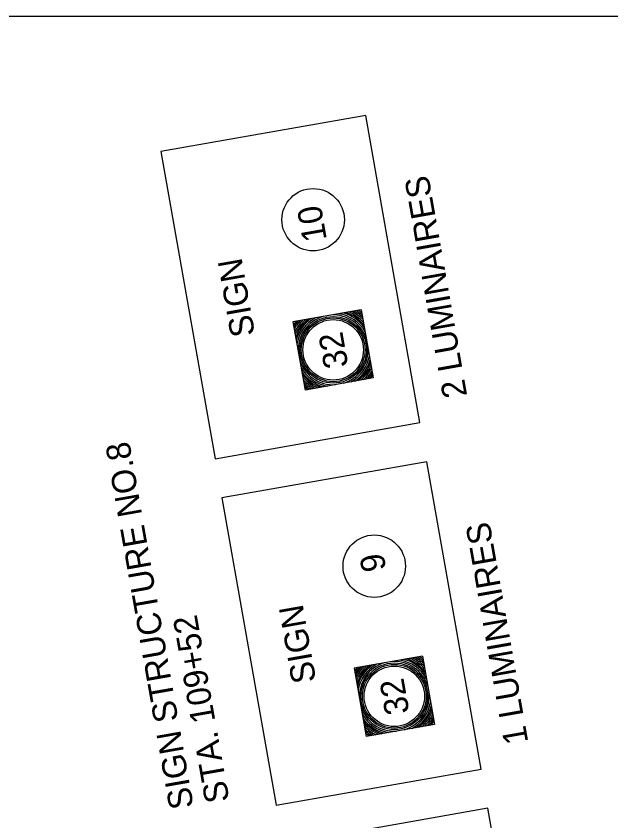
# Model space of a CAD drawing. Extents: x 36 to 2622, y -5330 to 219.
# Drawn here: x 679.8 to 753.4, y -4850.5 to -4750.8 of the extents above; entities that cross this region are included whole.
import ezdxf

# ---------------------------------------------------------------- set-up
doc = ezdxf.new("R2010")
doc.units = 0
doc.layers.add('1', color=7, linetype='Continuous')
doc.layers.add('2', color=7, linetype='Continuous')

msp = doc.modelspace()

# ---------------------------------------------------------------- linework, layer by layer
at = {"layer": '1'}
msp.add_line((75.856, -4750.83), (861.856, -4750.83), dxfattribs=at)
at = {"layer": '2'}
for points in [[(729.765, -4801.15), (723.058, -4763.122), (697.705, -4767.592), (704.411, -4805.62)], [(737.324, -4844.036), (730.618, -4806.01), (705.264, -4810.48), (711.971, -4848.506)], [(744.884, -4886.923), (738.177, -4848.895), (712.823, -4853.365), (719.53, -4891.392)]]:
    msp.add_lwpolyline(points, close=True, dxfattribs=at)
for points in [[(722.503, -4787.175), (714.053, -4788.665)], [(722.503, -4787.175), (723.992, -4795.627)], [(714.053, -4788.665), (715.542, -4797.117)], [(723.992, -4795.627), (715.542, -4797.117)], [(730.062, -4830.061), (721.615, -4831.55)], [(730.062, -4830.061), (731.552, -4838.513)], [(721.615, -4831.55), (723.104, -4840.002)], [(731.552, -4838.513), (723.104, -4840.002)]]:
    msp.add_lwpolyline(points, dxfattribs=at)
for centre, radius in [((716.546, -4776.037), 3.861), ((719.026, -4792.144), 4.125), ((719.026, -4792.144), 3.945), ((719.026, -4792.144), 3.739), ((724.105, -4818.923), 3.861), ((726.586, -4835.03), 4.125), ((726.586, -4835.03), 3.945), ((726.586, -4835.03), 3.739)]:
    msp.add_circle(centre, radius, dxfattribs=at)
for centre, radius, start, end in [((719.026, -4792.144), 4.319, 106.90383, 183.62104), ((719.026, -4792.144), 4.319, 16.90383, 93.09616), ((719.026, -4792.144), 4.529, 28.77474, 81.22525), ((719.026, -4792.144), 4.73, 34.96904, 75.03095), ((719.026, -4792.144), 4.884, 38.60357, 71.39642), ((719.026, -4792.144), 5.062, 42.10219, 67.8978), ((719.026, -4792.144), 5.257, 45.33768, 64.66231), ((719.026, -4792.144), 5.445, 48.04141, 61.95858), ((719.026, -4792.144), 5.617, 50.23096, 59.76903), ((719.026, -4792.144), 5.796, 52.28011, 57.71988), ((719.026, -4792.144), 5.796, 142.28011, 147.78717), ((719.026, -4792.144), 5.617, 140.23096, 149.84136), ((719.026, -4792.144), 5.445, 138.04141, 152.03679), ((719.026, -4792.144), 5.257, 135.33768, 154.74865), ((719.026, -4792.144), 5.062, 132.10219, 157.9954), ((719.026, -4792.144), 4.884, 128.60357, 161.50876), ((719.026, -4792.144), 4.73, 124.96904, 165.16259), ((719.026, -4792.144), 4.529, 118.77474, 171.40597), ((719.026, -4792.144), 4.319, 286.37895, 3.09616), ((719.026, -4792.144), 4.529, 298.59402, 351.22526), ((719.026, -4792.144), 4.319, 196.37895, 273.62103), ((719.026, -4792.144), 4.73, 304.8374, 345.03095), ((719.026, -4792.144), 4.884, 308.49123, 341.39643), ((719.026, -4792.144), 4.529, 208.59402, 261.40597), ((719.026, -4792.144), 4.73, 214.8374, 255.16259), ((719.026, -4792.144), 5.062, 312.00458, 337.8978), ((719.026, -4792.144), 5.257, 315.25134, 334.66231), ((719.026, -4792.144), 5.445, 317.96319, 331.95858), ((719.026, -4792.144), 5.617, 320.15863, 329.76903), ((719.026, -4792.144), 4.884, 218.49123, 251.50876), ((719.026, -4792.144), 5.062, 222.00458, 247.99539), ((719.026, -4792.144), 5.257, 225.25134, 244.74864), ((719.026, -4792.144), 5.796, 322.21282, 327.71989), ((719.026, -4792.144), 5.445, 227.96319, 242.03679), ((719.026, -4792.144), 5.617, 230.15863, 239.84136), ((719.026, -4792.144), 5.796, 232.21282, 237.78717), ((726.586, -4835.03), 4.319, 106.90383, 183.62104), ((726.586, -4835.03), 4.319, 16.90383, 93.09616), ((726.586, -4835.03), 4.529, 28.77474, 81.22525), ((726.586, -4835.03), 4.73, 34.96904, 75.03095), ((726.586, -4835.03), 4.884, 38.60357, 71.39642), ((726.586, -4835.03), 5.062, 42.10219, 67.8978), ((726.586, -4835.03), 5.257, 45.33768, 64.66231), ((726.586, -4835.03), 5.445, 48.04141, 61.95858), ((726.586, -4835.03), 5.617, 50.23096, 59.76903), ((726.586, -4835.03), 5.796, 52.28011, 57.71988), ((726.586, -4835.03), 5.796, 142.28011, 147.78717), ((726.586, -4835.03), 5.617, 140.23096, 149.84136), ((726.586, -4835.03), 5.445, 138.04141, 152.03679), ((726.586, -4835.03), 5.257, 135.33768, 154.74865), ((726.586, -4835.03), 5.062, 132.10219, 157.9954), ((726.586, -4835.03), 4.884, 128.60357, 161.50876), ((726.586, -4835.03), 4.73, 124.96904, 165.16259), ((726.586, -4835.03), 4.529, 118.77474, 171.40597), ((726.586, -4835.03), 4.319, 286.37895, 3.09616), ((726.586, -4835.03), 4.529, 298.59402, 351.22526), ((726.586, -4835.03), 4.319, 196.37895, 273.62103), ((726.586, -4835.03), 4.73, 304.8374, 345.03095), ((726.586, -4835.03), 4.884, 308.49123, 341.39643), ((726.586, -4835.03), 4.529, 208.59402, 261.40597), ((726.586, -4835.03), 4.73, 214.8374, 255.16259), ((726.586, -4835.03), 5.062, 312.00458, 337.8978), ((726.586, -4835.03), 5.257, 315.25134, 334.66231), ((726.586, -4835.03), 5.445, 317.96319, 331.95858), ((726.586, -4835.03), 5.617, 320.15863, 329.76903), ((726.586, -4835.03), 4.884, 218.49123, 251.50876), ((726.586, -4835.03), 5.062, 222.00458, 247.99539), ((726.586, -4835.03), 5.257, 225.25134, 244.74864), ((726.586, -4835.03), 5.796, 322.21282, 327.71989), ((726.586, -4835.03), 5.445, 227.96319, 242.03679), ((726.586, -4835.03), 5.617, 230.15863, 239.84136), ((726.586, -4835.03), 5.796, 232.21282, 237.78717)]:
    msp.add_arc(centre, radius, start, end, dxfattribs=at)

# ---------------------------------------------------------------- texts
for s, height, rotation, p in [('2 LUMINAIRES', 2.99549, 99.99999, (735.616, -4797.819)), ('10', 2.9955, 100, (718.255, -4778.49)), ('SIGN', 2.9955, 100, (709.372, -4790.258)), ('32', 2.9955, 100, (720.913, -4794.15)), ('SIGN STRUCTURE NO.8', 2.99549, 99.99999, (701.782, -4848.722)), ('1 LUMINAIRES', 2.99549, 99.99999, (743.176, -4840.705)), ('9', 2.995, 100, (725.598, -4819.347)), ('SIGN', 2.9955, 100, (716.934, -4833.144)), ('STA. 109+52', 2.99549, 99.99999, (706.204, -4847.944)), ('32', 2.9955, 100, (728.473, -4837.035))]:
    msp.add_text(s, height=height, rotation=rotation, dxfattribs=at).set_placement(p)

doc.saveas('drawing.dxf')
